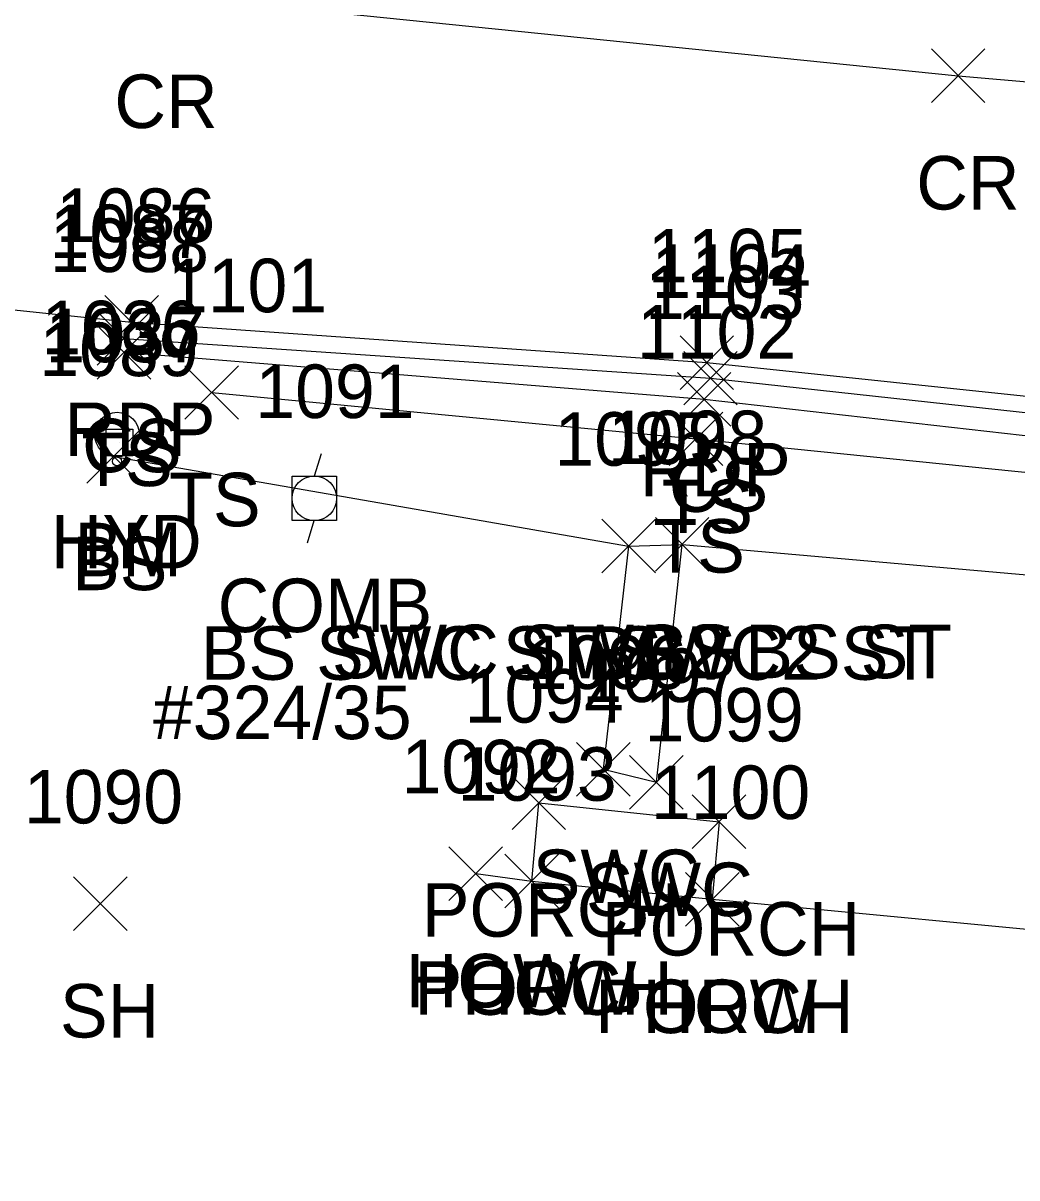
# Model space of a CAD drawing. Extents: x 1657482 to 1661439, y 647981 to 649041.
# Drawn here: x 1659694.57 to 1659731.72, y 648063.14 to 648106.3 of the extents above; entities that cross this region are included whole.
import ezdxf

# ---------------------------------------------------------------- set-up
doc = ezdxf.new("R2010")
doc.units = 0
for name, color, linetype in [('C_A', 7, 'Continuous'), ('C_I', 7, 'Continuous'), ('CPBM', 7, 'Continuous'), ('L_A', 7, 'Continuous'), ('L_I', 7, 'Continuous'), ('L_TIC', 7, 'Continuous'), ('LBC', 7, 'Continuous'), ('LBF', 7, 'Continuous'), ('LELB', 7, 'Continuous'), ('P_A', 7, 'Continuous'), ('P_I', 7, 'Continuous'), ('P_TIC', 7, 'Continuous'), ('PET', 7, 'Continuous'), ('PRC', 7, 'Continuous'), ('R_A', 7, 'Continuous'), ('R_I', 7, 'Continuous'), ('R_TIC', 7, 'Continuous'), ('RSW', 7, 'Continuous'), ('U_A', 7, 'Continuous'), ('U_C', 7, 'Continuous'), ('U_I', 7, 'Continuous'), ('UP', 7, 'Continuous'), ('UWFH', 7, 'Continuous')]:
    doc.layers.add(name, color=color, linetype=linetype)

msp = doc.modelspace()

# ---------------------------------------------------------------- linework, layer by layer
at = {"layer": 'CPBM'}
for p, q in [((1659697.679, 648090.126), (1659697.679, 648091.126)), ((1659697.679, 648091.126), (1659698.679, 648091.126)), ((1659698.679, 648091.126), (1659698.679, 648090.126)), ((1659698.182, 648090.627), (1659698.182, 648090.627)), ((1659698.182, 648090.627), (1659698.182, 648090.627)), ((1659698.679, 648090.126), (1659697.679, 648090.126))]:
    msp.add_line(p, q, dxfattribs=at)
at = {"layer": 'L_TIC'}
for points in [[(1659697.339, 648093.515), (1659699.339, 648095.515)], [(1659699.339, 648093.515), (1659697.339, 648095.515)], [(1659697.344, 648092.996), (1659699.344, 648094.996)], [(1659699.344, 648092.996), (1659697.344, 648094.996)], [(1659719.268, 648092.031), (1659721.268, 648094.031)], [(1659721.268, 648092.031), (1659719.268, 648094.031)], [(1659700.625, 648091.494), (1659702.625, 648093.494)], [(1659702.625, 648091.494), (1659700.625, 648093.494)], [(1659719.032, 648091.239), (1659721.032, 648093.239)], [(1659721.032, 648091.239), (1659719.032, 648093.239)], [(1659718.726, 648089.762), (1659720.726, 648091.762)], [(1659720.726, 648089.762), (1659718.726, 648091.762)], [(1659696.961, 648089.106), (1659698.961, 648091.106)], [(1659698.961, 648089.106), (1659696.961, 648091.106)], [(1659716.207, 648085.757), (1659718.207, 648087.757)], [(1659718.207, 648085.757), (1659716.207, 648087.757)], [(1659718.21, 648085.816), (1659720.21, 648087.816)], [(1659720.21, 648085.816), (1659718.21, 648087.816)], [(1659712.853, 648076.157), (1659714.853, 648078.157)], [(1659714.853, 648076.157), (1659712.853, 648078.157)], [(1659719.588, 648075.453), (1659721.588, 648077.453)], [(1659721.588, 648075.453), (1659719.588, 648077.453)], [(1659710.492, 648073.514), (1659712.492, 648075.514)], [(1659712.492, 648073.514), (1659710.492, 648075.514)], [(1659712.585, 648073.237), (1659714.585, 648075.237)], [(1659714.585, 648073.237), (1659712.585, 648075.237)], [(1659712.585, 648073.237), (1659714.585, 648075.237)], [(1659714.585, 648073.237), (1659712.585, 648075.237)], [(1659696.461, 648072.389), (1659698.461, 648074.389)], [(1659698.461, 648072.389), (1659696.461, 648074.389)], [(1659719.336, 648072.554), (1659721.336, 648074.554)], [(1659721.336, 648072.554), (1659719.336, 648074.554)], [(1659719.336, 648072.554), (1659721.336, 648074.554)], [(1659721.336, 648072.554), (1659719.336, 648074.554)]]:
    msp.add_lwpolyline(points, dxfattribs=at)
at = {"layer": 'LBC'}
msp.add_lwpolyline([(1659711.492, 648074.514), (1659713.585, 648074.237), (1659720.336, 648073.554), (1659736.024, 648072.064), (1659735.891, 648071.068)], dxfattribs=at)
at = {"layer": 'LBF'}
msp.add_lwpolyline([(1659713.585, 648074.237), (1659713.853, 648077.157), (1659720.588, 648076.453), (1659720.336, 648073.554)], dxfattribs=at)
at = {"layer": 'LELB'}
for points in [[(1659698.339, 648094.515), (1659720.268, 648093.031), (1659748.036, 648089.997), (1659760.398, 648089.114)], [(1659698.344, 648093.996), (1659720.032, 648092.239), (1659741.823, 648089.778), (1659745.757, 648089.198), (1659749.269, 648088.683), (1659760.143, 648087.603), (1659766.578, 648084.403), (1659767.572, 648074.522), (1659766.992, 648063.591), (1659763.81, 648063.143)], [(1659701.625, 648092.494), (1659719.726, 648090.762), (1659741.847, 648088.516), (1659745.757, 648089.198)], [(1659697.961, 648090.106), (1659717.207, 648086.757)], [(1659719.21, 648086.816), (1659742.71, 648084.749)]]:
    msp.add_lwpolyline(points, dxfattribs=at)
at = {"layer": 'P_TIC'}
for points in [[(1659728.526, 648103.331), (1659730.526, 648105.331)], [(1659730.526, 648103.331), (1659728.526, 648105.331)], [(1659697.631, 648094.118), (1659699.631, 648096.118)], [(1659699.631, 648094.118), (1659697.631, 648096.118)], [(1659719.133, 648092.609), (1659721.133, 648094.609)], [(1659721.133, 648092.609), (1659719.133, 648094.609)]]:
    msp.add_lwpolyline(points, dxfattribs=at)
at = {"layer": 'PET'}
msp.add_lwpolyline([(1659665.753, 648098.571), (1659698.631, 648095.118), (1659720.133, 648093.609), (1659748.043, 648090.675), (1659760.398, 648089.114), (1659764.367, 648088.405), (1659776.821, 648087.465), (1659799.28, 648086.136), (1659822.829, 648084.094)], dxfattribs=at)
at = {"layer": 'PRC'}
msp.add_lwpolyline([(1659666.144, 648110.534), (1659699.551, 648107.376), (1659729.526, 648104.331), (1659765.503, 648101.141), (1659792.988, 648098.376), (1659818.732, 648097.206), (1659849.225, 648095.841), (1659870.331, 648096.361), (1659894.597, 648099.456), (1659913.112, 648103.656), (1659935.294, 648110.794), (1659956.941, 648119.929), (1659978.865, 648130.6), (1660002.085, 648142.328), (1660031.609, 648158.263), (1660061.231, 648174.691), (1660097.076, 648195.768), (1660113.884, 648205.485), (1660151.727, 648227.302), (1660188.688, 648248.658)], dxfattribs=at)
at = {"layer": 'R_TIC'}
for points in [[(1659716.207, 648085.757), (1659718.207, 648087.757)], [(1659718.207, 648085.757), (1659716.207, 648087.757)], [(1659716.207, 648085.757), (1659718.207, 648087.757)], [(1659718.207, 648085.757), (1659716.207, 648087.757)], [(1659718.21, 648085.816), (1659720.21, 648087.816)], [(1659720.21, 648085.816), (1659718.21, 648087.816)], [(1659718.21, 648085.816), (1659720.21, 648087.816)], [(1659720.21, 648085.816), (1659718.21, 648087.816)], [(1659715.261, 648077.412), (1659717.261, 648079.412)], [(1659717.261, 648077.412), (1659715.261, 648079.412)], [(1659717.247, 648076.926), (1659719.247, 648078.926)], [(1659719.247, 648076.926), (1659717.247, 648078.926)]]:
    msp.add_lwpolyline(points, dxfattribs=at)
at = {"layer": 'RSW'}
for points in [[(1659717.207, 648086.757), (1659716.261, 648078.412), (1659718.247, 648077.926), (1659719.21, 648086.816)], [(1659717.207, 648086.757), (1659719.21, 648086.816)]]:
    msp.add_lwpolyline(points, dxfattribs=at)
at = {"layer": 'UP'}
for p, q in [((1659705.71, 648090.205), (1659705.46, 648089.372)), ((1659704.627, 648087.705), (1659704.627, 648089.372)), ((1659704.627, 648089.372), (1659706.293, 648089.372)), ((1659706.293, 648089.372), (1659706.293, 648087.705)), ((1659705.46, 648088.539), (1659705.46, 648088.539)), ((1659706.293, 648087.705), (1659704.627, 648087.705)), ((1659705.21, 648086.872), (1659705.46, 648087.705))]:
    msp.add_line(p, q, dxfattribs=at)
msp.add_circle((1659705.46, 648088.539), 0.833, dxfattribs=at)
at = {"layer": 'UWFH'}
msp.add_line((1659698.084, 648090.921), (1659698.084, 648090.921), dxfattribs=at)
for centre, radius in [((1659698.084, 648090.921), 0.833), ((1659697.084, 648090.921), 0.167), ((1659699.084, 648090.921), 0.167), ((1659698.084, 648089.921), 0.167)]:
    msp.add_circle(centre, radius, dxfattribs=at)

# ---------------------------------------------------------------- texts
at = {"layer": 'C_A'}
msp.add_text('BM', height=2, dxfattribs=at).set_placement((1659696.497, 648085.627))
at = {"layer": 'C_I'}
msp.add_text('1037', height=2, dxfattribs=at).set_placement((1659695.411, 648093.627))
at = {"layer": 'L_A'}
for s, p in [('CS', (1659696.78, 648089.515)), ('TS', (1659696.753, 648088.996)), ('CS', (1659718.709, 648088.031)), ('TS', (1659700.035, 648087.494)), ('TS', (1659718.441, 648087.239)), ('TS', (1659718.136, 648085.762)), ('BS', (1659696.402, 648085.106)), ('BS', (1659715.648, 648081.757)), ('BS', (1659717.651, 648081.816)), ('PORCH', (1659709.475, 648072.157)), ('PORCH', (1659716.21, 648071.453)), ('HOW', (1659708.878, 648069.514)), ('PORCH', (1659709.207, 648069.237)), ('HOW', (1659710.971, 648069.237)), ('SH', (1659695.95, 648068.389)), ('PORCH', (1659715.958, 648068.554)), ('HOW', (1659717.722, 648068.554))]:
    msp.add_text(s, height=2, dxfattribs=at).set_placement(p)
at = {"layer": 'L_I'}
for s, p in [('1087', (1659695.568, 648097.515)), ('1088', (1659695.572, 648096.996)), ('1104', (1659718.064, 648096.031)), ('1101', (1659699.988, 648095.494)), ('1103', (1659717.827, 648095.239)), ('1102', (1659717.522, 648093.762)), ('1089', (1659695.182, 648093.106)), ('1095', (1659714.436, 648089.757)), ('1098', (1659716.438, 648089.816)), ('1094', (1659711.081, 648080.157)), ('1099', (1659717.809, 648079.453)), ('1092', (1659708.721, 648077.514)), ('1093', (1659710.814, 648077.237)), ('1093', (1659710.814, 648077.237)), ('1100', (1659718.045, 648076.554)), ('1100', (1659718.045, 648076.554)), ('1090', (1659694.603, 648076.389))]:
    msp.add_text(s, height=2, dxfattribs=at).set_placement(p)
at = {"layer": 'P_A'}
for s, p in [('CR', (1659697.984, 648102.376)), ('CR', (1659727.959, 648099.331)), ('RDP', (1659696.119, 648090.118)), ('RDP', (1659717.621, 648088.609))]:
    msp.add_text(s, height=2, dxfattribs=at).set_placement(p)
at = {"layer": 'P_I'}
for s, p in [('1086', (1659695.804, 648098.118)), ('1105', (1659717.929, 648096.609))]:
    msp.add_text(s, height=2, dxfattribs=at).set_placement(p)
at = {"layer": 'R_A'}
for s, p in [('BS SWC ST SWC2 ST', (1659701.215, 648081.757)), ('BS SWC ST SWC2 ST', (1659701.215, 648081.757)), ('SWC SWC2 BS ST', (1659706.115, 648081.816)), ('SWC SWC2 BS ST', (1659706.115, 648081.816)), ('SWC', (1659713.623, 648073.412)), ('SWC', (1659715.61, 648072.926))]:
    msp.add_text(s, height=2, dxfattribs=at).set_placement(p)
at = {"layer": 'R_I'}
for s, p in [('1095', (1659714.436, 648089.757)), ('1095', (1659714.436, 648089.757)), ('1098', (1659716.438, 648089.816)), ('1098', (1659716.438, 648089.816)), ('1096', (1659713.435, 648081.412)), ('1097', (1659715.476, 648080.926))]:
    msp.add_text(s, height=2, dxfattribs=at).set_placement(p)
at = {"layer": 'U_A'}
for s, p in [('HYD', (1659695.604, 648085.921)), ('COMB', (1659701.846, 648083.539))]:
    msp.add_text(s, height=2, dxfattribs=at).set_placement(p)
at = {"layer": 'U_C'}
msp.add_text('#324/35', height=2, dxfattribs=at).set_placement((1659699.429, 648079.539))
at = {"layer": 'U_I'}
for s, p in [('1036', (1659695.258, 648093.921)), ('1091', (1659703.256, 648091.539))]:
    msp.add_text(s, height=2, dxfattribs=at).set_placement(p)

doc.saveas('drawing.dxf')
